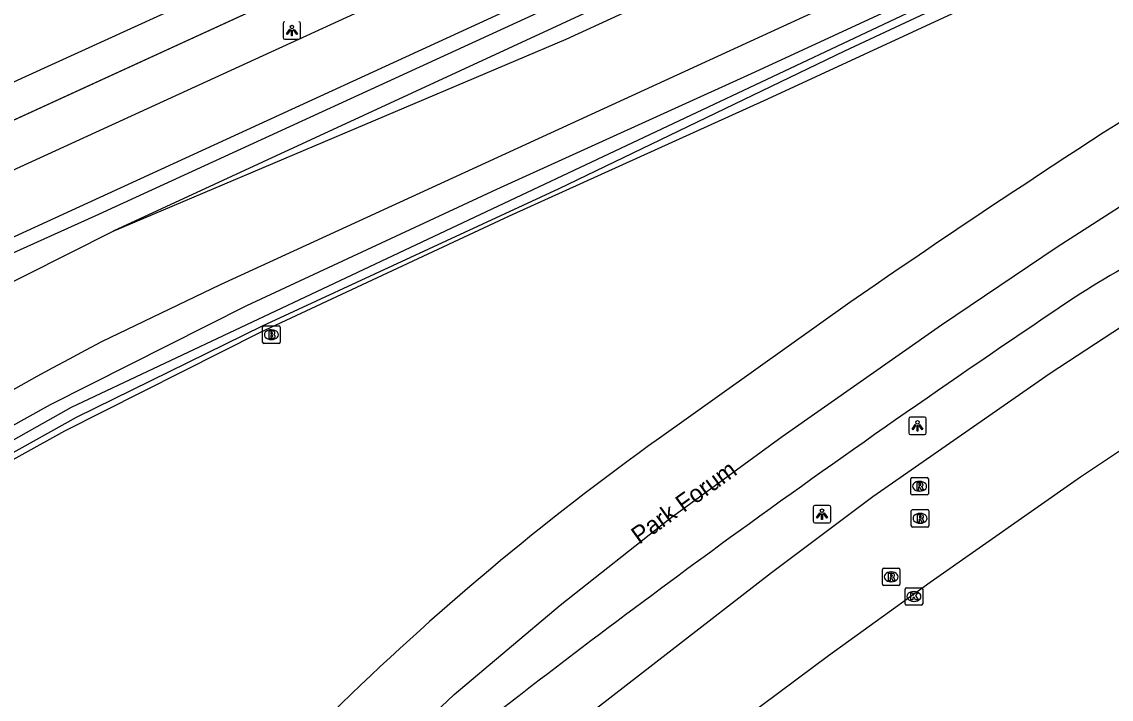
# Model space of a CAD drawing. Extents: x 154324 to 155743, y 382939 to 384183.
# Drawn here: x 155121.7 to 155184, y 383932 to 383970.8 of the extents above; entities that cross this region are included whole.
import ezdxf

# ---------------------------------------------------------------- set-up
doc = ezdxf.new("R2010")
doc.units = 0
for name, color, linetype in [('IMGEO_Brandkraan', 7, 'Continuous'), ('IMGEO_Fietspad_gesloten', 7, 'Continuous'), ('IMGEO_Groenvoorziening', 7, 'Continuous'), ('IMGEO_Hek', 7, 'Continuous'), ('IMGEO_Kolk', 7, 'Continuous'), ('IMGEO_Lichtpunt', 7, 'Continuous'), ('IMGEO_Openbare_ruimte_label', 7, 'Continuous'), ('IMGEO_Rijbaan_lokaal_gesloten', 7, 'Continuous'), ('IMGEO_Rijbaan_regionaal_gesloten', 7, 'Continuous'), ('IMGEO_Rioolput', 7, 'Continuous'), ('IMGEO_Waterloop', 7, 'Continuous')]:
    doc.layers.add(name, color=color, linetype=linetype)

msp = doc.modelspace()

# ---------------------------------------------------------------- linework, layer by layer
at = {"layer": 'IMGEO_Brandkraan'}
for p, q in [((155135.434, 383952.47), (155135.434, 383953.322)), ((155135.509, 383953.396), (155136.361, 383953.396)), ((155135.922, 383953.176), (155135.947, 383953.176)), ((155136.435, 383953.322), (155136.435, 383952.47)), ((155135.945, 383952.616), (155135.92, 383952.616)), ((155136.361, 383952.396), (155135.509, 383952.396))]:
    msp.add_line(p, q, dxfattribs=at)
for points in [[(155135.434, 383952.47), (155135.434, 383953.322)], [(155135.509, 383953.396), (155136.361, 383953.396)], [(155136.435, 383953.322), (155136.435, 383952.47)], [(155135.782, 383953.096), (155135.782, 383952.696), (155135.995, 383952.696)], [(155136.013, 383953.096), (155135.782, 383953.096)], [(155135.961, 383953.015), (155135.907, 383953.015), (155135.907, 383952.939)], [(155135.907, 383952.939), (155135.96, 383952.939)], [(155135.969, 383952.863), (155135.907, 383952.863), (155135.907, 383952.782)], [(155135.907, 383952.782), (155135.969, 383952.782)], [(155136.361, 383952.396), (155135.509, 383952.396)]]:
    msp.add_lwpolyline(points, dxfattribs=at)
for centre, radius, start, end in [((155135.511, 383953.32), 0.0765, 91.55205, 178.44795), ((155135.511, 383953.32), 0.0765, 91.55205, 178.44795), ((155136.359, 383953.32), 0.0765, 1.55205, 88.44795), ((155136.359, 383953.32), 0.0765, 1.55205, 88.44795), ((155135.962, 383952.977), 0.0379, 267.82845, 90.93552), ((155135.97, 383952.822), 0.0404, 269.87594, 90.50774), ((155136.001, 383952.947), 0.251, 268.66757, 293.53466), ((155136.017, 383952.951), 0.145, 59.4692, 91.53667), ((155136.042, 383952.998), 0.0922, 285.51372, 58.15012), ((155136.047, 383952.806), 0.105, 301.31148, 78.98903), ((155135.511, 383952.472), 0.0765, 181.55205, 268.44795), ((155135.511, 383952.472), 0.0765, 181.55205, 268.44795), ((155136.359, 383952.472), 0.0765, 271.55205, 358.44795), ((155136.359, 383952.472), 0.0765, 271.55205, 358.44795)]:
    msp.add_arc(centre, radius, start, end, dxfattribs=at)
for centre, major_axis, ratio, start_param, end_param in [((155135.921, 383952.896), (-0.387, 0.002), 0.722429, 4.712389, 7.853982), ((155135.946, 383952.896), (-0.39, 0.002), 0.717154, 1.570796, 4.712389)]:
    msp.add_ellipse(centre, major_axis=major_axis, ratio=ratio, start_param=start_param, end_param=end_param, dxfattribs=at)
at = {"layer": 'IMGEO_Fietspad_gesloten'}
for points in [[(155080.941, 383943.909), (155153.249, 383977.036), (155322.262, 384054.741), (155387.573, 384084.704)], [(155389.956, 384081.901), (155107.896, 383952.388), (155082.34, 383940.7)]]:
    msp.add_lwpolyline(points, dxfattribs=at)
at = {"layer": 'IMGEO_Groenvoorziening'}
for points in [[(155079.739, 383946.19), (155178.427, 383991.44), (155254.498, 384026.37), (155303.667, 384048.873), (155397.138, 384091.79), (155462.373, 384121.668), (155554.91, 384164.088), (155566.214, 384169.267)], [(155068.64, 383933.902), (155125.852, 383959.693), (155390.548, 384081.204), (155436.679, 384102.381), (155567.788, 384162.639)], [(155568.361, 384160.227), (155558.223, 384156.124), (155535.377, 384146.692), (155391.259, 384080.368), (155353.768, 384063.115), (155183.941, 383985.208), (155126.877, 383958.819)], [(155118.285, 383946.124), (155123.303, 383948.901), (155134.537, 383954.573), (155148.835, 383961.231), (155163.617, 383967.939), (155213.131, 383990.84), (155225.593, 383996.741), (155232.744, 383999.887), (155240.567, 384003.683), (155245.77, 384006.066), (155281.079, 384022.24), (155335.13, 384047.346), (155342.51, 384050.527)], [(155343.202, 384048.958), (155335.832, 384045.781), (155281.796, 384020.682), (155246.475, 384004.503), (155241.299, 384002.132), (155233.464, 383998.33), (155226.305, 383995.181), (155213.857, 383989.287), (155164.333, 383966.381), (155149.551, 383959.673), (155135.285, 383953.03), (155124.105, 383947.385), (155119.195, 383944.668)]]:
    msp.add_lwpolyline(points, dxfattribs=at)
at = {"layer": 'IMGEO_Hek'}
msp.add_lwpolyline([(154996.514, 383908.03), (155178.427, 383991.44)], dxfattribs=at)
at = {"layer": 'IMGEO_Kolk'}
for p, q in [((155172.206, 383937.491), (155172.206, 383938.343)), ((155172.281, 383938.417), (155173.133, 383938.417)), ((155172.694, 383938.197), (155172.719, 383938.197)), ((155173.207, 383938.343), (155173.207, 383937.491)), ((155172.717, 383937.637), (155172.692, 383937.637)), ((155173.133, 383937.417), (155172.281, 383937.417))]:
    msp.add_line(p, q, dxfattribs=at)
for points in [[(155172.206, 383937.491), (155172.206, 383938.343)], [(155172.281, 383938.417), (155173.133, 383938.417)], [(155173.207, 383938.343), (155173.207, 383937.491)], [(155172.527, 383938.117), (155172.65, 383938.117), (155172.65, 383937.966), (155172.78, 383938.117), (155172.944, 383938.117), (155172.798, 383937.966), (155172.951, 383937.717), (155172.799, 383937.717), (155172.714, 383937.881), (155172.65, 383937.814), (155172.65, 383937.717), (155172.527, 383937.717), (155172.527, 383938.117)], [(155173.133, 383937.417), (155172.281, 383937.417)]]:
    msp.add_lwpolyline(points, dxfattribs=at)
for centre, start, end in [((155172.283, 383938.341), 91.55205, 178.44795), ((155172.283, 383938.341), 91.55205, 178.44795), ((155173.131, 383938.341), 1.55205, 88.44795), ((155173.131, 383938.341), 1.55205, 88.44795), ((155172.283, 383937.493), 181.55205, 268.44795), ((155172.283, 383937.493), 181.55205, 268.44795), ((155173.131, 383937.493), 271.55205, 358.44795), ((155173.131, 383937.493), 271.55205, 358.44795)]:
    msp.add_arc(centre, 0.0765, start, end, dxfattribs=at)
for centre, major_axis, ratio, start_param, end_param in [((155172.693, 383937.917), (-0.387, 0.002), 0.722429, 4.712389, 7.853982), ((155172.718, 383937.917), (-0.39, 0.002), 0.717154, 1.570796, 4.712389)]:
    msp.add_ellipse(centre, major_axis=major_axis, ratio=ratio, start_param=start_param, end_param=end_param, dxfattribs=at)
at = {"layer": 'IMGEO_Lichtpunt'}
for p, q in [((155136.611, 383970.71), (155136.611, 383969.903)), ((155136.611, 383970.71), (155136.611, 383969.903)), ((155137.607, 383969.903), (155137.607, 383970.71)), ((155137.607, 383969.903), (155137.607, 383970.71)), ((155136.705, 383969.809), (155137.513, 383969.809)), ((155136.705, 383969.809), (155137.513, 383969.809)), ((155173.311, 383948.181), (155172.503, 383948.181)), ((155173.311, 383948.181), (155172.503, 383948.181)), ((155172.409, 383948.086), (155172.409, 383947.279)), ((155172.409, 383948.086), (155172.409, 383947.279)), ((155173.405, 383947.279), (155173.405, 383948.086)), ((155173.405, 383947.279), (155173.405, 383948.086)), ((155172.503, 383947.185), (155173.311, 383947.185)), ((155172.503, 383947.185), (155173.311, 383947.185)), ((155166.947, 383943.032), (155166.947, 383942.225)), ((155166.947, 383943.032), (155166.947, 383942.225)), ((155167.849, 383943.127), (155167.041, 383943.127)), ((155167.849, 383943.127), (155167.041, 383943.127)), ((155167.943, 383942.225), (155167.943, 383943.032)), ((155167.943, 383942.225), (155167.943, 383943.032)), ((155167.041, 383942.131), (155167.849, 383942.131)), ((155167.041, 383942.131), (155167.849, 383942.131))]:
    msp.add_line(p, q, dxfattribs=at)
for points in [[(155136.985, 383970.374), (155137.024, 383970.346), (155136.836, 383970.084), (155136.798, 383970.111), (155136.985, 383970.374)], [(155137.087, 383970.326), (155137.134, 383970.326), (155137.134, 383970.004), (155137.087, 383970.004), (155137.087, 383970.326)], [(155137.197, 383970.346), (155137.235, 383970.373), (155137.422, 383970.111), (155137.383, 383970.083), (155137.197, 383970.346)], [(155172.783, 383947.75), (155172.822, 383947.722), (155172.634, 383947.46), (155172.596, 383947.487), (155172.783, 383947.75)], [(155172.885, 383947.702), (155172.932, 383947.702), (155172.932, 383947.38), (155172.885, 383947.38), (155172.885, 383947.702)], [(155172.995, 383947.722), (155173.033, 383947.749), (155173.22, 383947.487), (155173.181, 383947.459), (155172.995, 383947.722)], [(155167.321, 383942.696), (155167.36, 383942.668), (155167.172, 383942.406), (155167.134, 383942.433), (155167.321, 383942.696)], [(155167.423, 383942.648), (155167.47, 383942.648), (155167.47, 383942.326), (155167.423, 383942.326), (155167.423, 383942.648)], [(155167.533, 383942.668), (155167.571, 383942.695), (155167.758, 383942.433), (155167.719, 383942.405), (155167.533, 383942.668)]]:
    msp.add_lwpolyline(points, dxfattribs=at)
for centre in [(155137.11, 383970.508), (155172.908, 383947.884), (155167.446, 383942.83)]:
    msp.add_circle(centre, 0.0994, dxfattribs=at)
for centre, start, end in [((155136.705, 383970.71), 90, 180), ((155136.705, 383970.71), 90, 180), ((155137.513, 383970.71), 0, 90), ((155137.513, 383970.71), 0, 90), ((155136.705, 383969.903), 180, 270), ((155136.705, 383969.903), 180, 270), ((155137.513, 383969.903), 270, 0), ((155137.513, 383969.903), 270, 360), ((155172.503, 383948.086), 90, 180), ((155172.503, 383948.086), 90, 180), ((155173.311, 383948.086), 0, 90), ((155173.311, 383948.086), 0, 90), ((155172.503, 383947.279), 180, 270), ((155172.503, 383947.279), 180, 270), ((155173.311, 383947.279), 270, 0), ((155173.311, 383947.279), 270, 360), ((155167.041, 383943.032), 90, 180), ((155167.041, 383943.032), 90, 180), ((155167.849, 383943.032), 0, 90), ((155167.849, 383943.032), 0, 90), ((155167.041, 383942.225), 180, 270), ((155167.041, 383942.225), 180, 270), ((155167.849, 383942.225), 270, 0), ((155167.849, 383942.225), 270, 360)]:
    msp.add_arc(centre, 0.0946, start, end, dxfattribs=at)
at = {"layer": 'IMGEO_Rijbaan_lokaal_gesloten'}
for points in [[(155565.781, 384171.091), (155345.515, 384070.104), (155302.819, 384050.582), (155259.756, 384030.849), (155227.42, 384015.974), (155215.147, 384010.329), (155198.929, 384002.897), (155192.608, 384000), (155164.663, 383987.193), (155121.842, 383967.653), (155000, 383911.736), (154979.375, 383902.278), (154932.826, 383880.986), (154892.012, 383862.235), (154851.378, 383843.667), (154815.848, 383827.359), (154647.11, 383750), (154617.486, 383736.421)], [(155138.407, 383905.368), (155138.686, 383905.811), (155148.632, 383917.845), (155151.051, 383920.585), (155153.632, 383923.181), (155156.346, 383925.646), (155159.165, 383927.997), (155162.06, 383930.25), (155167.822, 383934.537), (155173.642, 383938.73), (155182.24, 383944.758), (155186.065, 383947.326), (155197.209, 383954.523), (155208.019, 383961.01), (155216.947, 383966.211)], [(155194.401, 383959.769), (155180.51, 383950.671), (155170.363, 383943.609), (155164.546, 383939.275), (155152.834, 383930.186), (155149.95, 383927.749), (155147.219, 383925.163), (155144.709, 383922.37), (155133.588, 383908.721)]]:
    msp.add_lwpolyline(points, dxfattribs=at)
at = {"layer": 'IMGEO_Rijbaan_regionaal_gesloten'}
for points in [[(155126.877, 383958.819), (155152.797, 383969.816), (155391.893, 384079.622)], [(155394.955, 384076.021), (155392.931, 384075.139), (155245.217, 384007.292), (155133.002, 383955.75), (155126.218, 383952.481)], [(155127.637, 383909.547), (155129.694, 383913.816), (155135.047, 383920.931), (155140.545, 383926.751), (155146.389, 383932.297), (155152.454, 383937.425), (155158.731, 383942.381), (155165.173, 383947.069), (155174.282, 383953.456), (155180.905, 383957.932), (155196.341, 383967.819), (155207.358, 383974.486), (155208.596, 383974.479)], [(155116.785, 383953.754), (155126.877, 383958.819)], [(155169.042, 383954.737), (155158.138, 383946.978)]]:
    msp.add_lwpolyline(points, dxfattribs=at)
for centre, radius, start, end in [((155481.723, 383503.313), 549.138, 121.79595, 124.70856), ((155226.572, 383884.581), 83.419, 118.05219, 122.35264), ((155550.304, 383405.836), 661.313, 123.850715, 125.881835), ((155223.884, 383765.328), 211.104, 117.5579, 126.68007), ((155251.621, 383816.498), 160.512, 125.62005, 134.36056), ((155500.921, 383476.271), 575.303, 126.008507, 127.98532)]:
    msp.add_arc(centre, radius, start, end, dxfattribs=at)
at = {"layer": 'IMGEO_Rioolput'}
for p, q in [((155172.531, 383943.799), (155172.531, 383944.651)), ((155172.606, 383944.725), (155173.458, 383944.725)), ((155173.019, 383944.505), (155173.044, 383944.505)), ((155173.532, 383944.651), (155173.532, 383943.799)), ((155173.042, 383943.945), (155173.017, 383943.945)), ((155173.458, 383943.725), (155172.606, 383943.725)), ((155172.556, 383941.96), (155172.556, 383942.812)), ((155172.631, 383942.886), (155173.483, 383942.886)), ((155173.044, 383942.666), (155173.069, 383942.666)), ((155173.557, 383942.812), (155173.557, 383941.96)), ((155173.067, 383942.106), (155173.042, 383942.106)), ((155173.483, 383941.886), (155172.631, 383941.886)), ((155170.904, 383938.612), (155170.904, 383939.464)), ((155170.979, 383939.538), (155171.831, 383939.538)), ((155171.905, 383939.464), (155171.905, 383938.612)), ((155171.392, 383939.318), (155171.417, 383939.318)), ((155171.831, 383938.538), (155170.979, 383938.538)), ((155171.415, 383938.758), (155171.39, 383938.758))]:
    msp.add_line(p, q, dxfattribs=at)
for points in [[(155172.531, 383943.799), (155172.531, 383944.651)], [(155172.606, 383944.725), (155173.458, 383944.725)], [(155173.12, 383944.423), (155172.868, 383944.425), (155172.868, 383944.025)], [(155173.532, 383944.651), (155173.532, 383943.799)], [(155172.868, 383944.025), (155172.992, 383944.025), (155172.992, 383944.187), (155173.003, 383944.187)], [(155173.046, 383944.344), (155172.992, 383944.344), (155172.992, 383944.263)], [(155172.992, 383944.263), (155173.044, 383944.263)], [(155173.05, 383944.158), (155173.121, 383944.025), (155173.261, 383944.025), (155173.196, 383944.151)], [(155173.458, 383943.725), (155172.606, 383943.725)], [(155172.556, 383941.96), (155172.556, 383942.812)], [(155172.631, 383942.886), (155173.483, 383942.886)], [(155173.145, 383942.584), (155172.893, 383942.586), (155172.893, 383942.186)], [(155173.557, 383942.812), (155173.557, 383941.96)], [(155172.893, 383942.186), (155173.017, 383942.186), (155173.017, 383942.348), (155173.028, 383942.348)], [(155173.071, 383942.505), (155173.017, 383942.505), (155173.017, 383942.424)], [(155173.017, 383942.424), (155173.069, 383942.424)], [(155173.075, 383942.319), (155173.146, 383942.186), (155173.286, 383942.186), (155173.221, 383942.312)], [(155173.483, 383941.886), (155172.631, 383941.886)], [(155170.904, 383938.612), (155170.904, 383939.464)], [(155170.979, 383939.538), (155171.831, 383939.538)], [(155171.905, 383939.464), (155171.905, 383938.612)], [(155171.493, 383939.236), (155171.241, 383939.238), (155171.241, 383938.838)], [(155171.241, 383938.838), (155171.365, 383938.838), (155171.365, 383939), (155171.376, 383939)], [(155171.419, 383939.157), (155171.365, 383939.157), (155171.365, 383939.076)], [(155171.365, 383939.076), (155171.417, 383939.076)], [(155171.423, 383938.971), (155171.494, 383938.838), (155171.634, 383938.838), (155171.569, 383938.964)], [(155171.831, 383938.538), (155170.979, 383938.538)]]:
    msp.add_lwpolyline(points, dxfattribs=at)
for centre, radius, start, end in [((155172.608, 383944.649), 0.0765, 91.55205, 178.44795), ((155172.608, 383944.649), 0.0765, 91.55205, 178.44795), ((155173.119, 383944.313), 0.109, 350.36119, 89.41601), ((155173.456, 383944.649), 0.0765, 1.55205, 88.44795), ((155173.456, 383944.649), 0.0765, 1.55205, 88.44795), ((155172.608, 383943.801), 0.0765, 181.55205, 268.44795), ((155172.608, 383943.801), 0.0765, 181.55205, 268.44795), ((155173.002, 383944.134), 0.0533, 26.02933, 88.69889), ((155173.028, 383944.452), 0.19, 274.7715, 282.96867), ((155173.052, 383944.248), 0.0964, 77.00612, 93.18647), ((155173.066, 383944.305), 0.0378, 276.66336, 79.67722), ((155173.117, 383944.313), 0.112, 277.58423, 350.98172), ((155173.101, 383944.098), 0.108, 29.51342, 73.79051), ((155173.456, 383943.801), 0.0765, 271.55205, 358.44795), ((155173.456, 383943.801), 0.0765, 271.55205, 358.44795), ((155172.633, 383942.81), 0.0765, 91.55205, 178.44795), ((155172.633, 383942.81), 0.0765, 91.55205, 178.44795), ((155173.144, 383942.474), 0.109, 350.36119, 89.41601), ((155173.481, 383942.81), 0.0765, 1.55205, 88.44795), ((155173.481, 383942.81), 0.0765, 1.55205, 88.44795), ((155172.633, 383941.962), 0.0765, 181.55205, 268.44795), ((155172.633, 383941.962), 0.0765, 181.55205, 268.44795), ((155173.027, 383942.295), 0.0533, 26.02933, 88.69889), ((155173.053, 383942.613), 0.19, 274.7715, 282.96867), ((155173.077, 383942.409), 0.0964, 77.00612, 93.18647), ((155173.091, 383942.466), 0.0378, 276.66336, 79.67722), ((155173.142, 383942.474), 0.112, 277.58423, 350.98172), ((155173.126, 383942.259), 0.108, 29.51342, 73.79051), ((155173.481, 383941.962), 0.0765, 271.55205, 358.44795), ((155173.481, 383941.962), 0.0765, 271.55205, 358.44795), ((155170.981, 383939.462), 0.0765, 91.55205, 178.44795), ((155170.981, 383939.462), 0.0765, 91.55205, 178.44795), ((155171.829, 383939.462), 0.0765, 1.55205, 88.44795), ((155171.829, 383939.462), 0.0765, 1.55205, 88.44795), ((155171.375, 383938.947), 0.0533, 26.02933, 88.69889), ((155171.401, 383939.265), 0.19, 274.7715, 282.96867), ((155171.425, 383939.061), 0.0964, 77.00612, 93.18647), ((155171.439, 383939.118), 0.0378, 276.66336, 79.67722), ((155171.492, 383939.126), 0.109, 350.36119, 89.41601), ((155171.49, 383939.126), 0.112, 277.58423, 350.98172), ((155171.474, 383938.911), 0.108, 29.51342, 73.79051), ((155170.981, 383938.614), 0.0765, 181.55205, 268.44795), ((155170.981, 383938.614), 0.0765, 181.55205, 268.44795), ((155171.829, 383938.614), 0.0765, 271.55205, 358.44795), ((155171.829, 383938.614), 0.0765, 271.55205, 358.44795)]:
    msp.add_arc(centre, radius, start, end, dxfattribs=at)
for centre, major_axis, ratio, start_param, end_param in [((155173.018, 383944.225), (-0.387, 0.002), 0.722429, 4.712389, 7.853982), ((155173.043, 383944.225), (-0.39, 0.002), 0.717154, 1.570796, 4.712389), ((155173.043, 383942.386), (-0.387, 0.002), 0.722429, 4.712389, 7.853982), ((155173.068, 383942.386), (-0.39, 0.002), 0.717154, 1.570796, 4.712389), ((155171.391, 383939.038), (-0.387, 0.002), 0.722429, 4.712389, 7.853982), ((155171.416, 383939.038), (-0.39, 0.002), 0.717154, 1.570796, 4.712389)]:
    msp.add_ellipse(centre, major_axis=major_axis, ratio=ratio, start_param=start_param, end_param=end_param, dxfattribs=at)
at = {"layer": 'IMGEO_Waterloop'}
for points in [[(155075.55, 383904.232), (155082.726, 383903.913), (155089.478, 383902.725), (155099.372, 383899.688), (155100.518, 383899.667), (155101.919, 383900.347), (155105.932, 383905.506), (155106.718, 383906.759), (155107.036, 383909.306), (155106.229, 383916.419), (155105.465, 383918.202), (155103.257, 383919.816), (155101.686, 383921.387), (155101.983, 383922.321), (155104.106, 383922.364), (155106.272, 383921.642), (155106.282, 383923.192), (155107.079, 383928.616), (155108.48, 383932.99), (155111.282, 383937.873), (155113.448, 383940.761), (155117.227, 383944.667), (155124.488, 383948.744), (155189.711, 383979.529)], [(155188.427, 383978.33), (155168.724, 383969.115), (155152.376, 383961.238), (155135.412, 383953.383), (155124.764, 383948.149), (155117.535, 383944.126)]]:
    msp.add_lwpolyline(points, dxfattribs=at)

# ---------------------------------------------------------------- texts
at = {"layer": 'IMGEO_Openbare_ruimte_label'}
msp.add_text('Park Forum', height=1, rotation=35.72413, dxfattribs=at).set_placement((155156.992, 383940.87))

doc.saveas('drawing.dxf')
